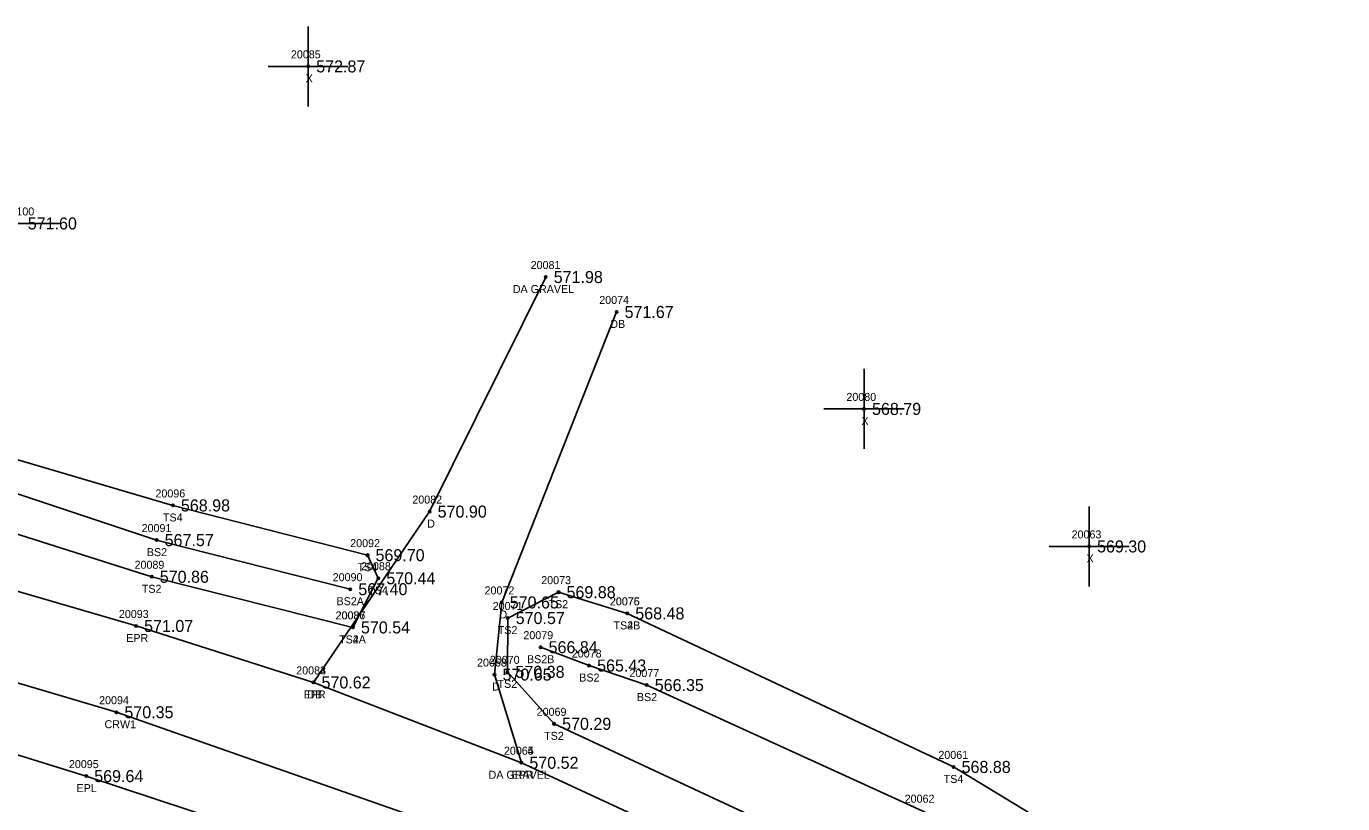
# Model space of a CAD drawing. Extents: x 1530159 to 1531652, y 877045 to 877724.
# Drawn here: x 1531368.6 to 1531533, y 877234.2 to 877331.3 of the extents above; entities that cross this region are included whole.
import ezdxf

# ---------------------------------------------------------------- set-up
doc = ezdxf.new("R2010")
doc.units = 0
for name, color, linetype in [('RD_DTM_BkLn1', 7, 'Continuous'), ('RD_DTM_BkLn2', 7, 'Continuous'), ('RD_DTM_BkLn_txCode', 7, 'Continuous'), ('RD_EX_Driveway', 7, 'Continuous'), ('RD_EX_Driveway_txCode', 7, 'Continuous'), ('RD_EX_Misc', 7, 'Continuous'), ('RD_EX_Misc_txCode', 7, 'Continuous'), ('RD_EX_Road', 7, 'Continuous'), ('RD_EX_Road_txCode', 7, 'Continuous'), ('RD_EX_TX_Driveway_ELEV', 7, 'Continuous'), ('RD_EX_TX_Misc_ELEV', 7, 'Continuous'), ('RD_EX_TX_Road_ELEV', 7, 'Continuous'), ('RD_HC_Survey_ELEV', 7, 'Continuous'), ('RD_HC_Survey_txCode', 7, 'Continuous'), ('RD_SMD_Locator', 7, 'Continuous')]:
    doc.layers.add(name, color=color, linetype=linetype)

msp = doc.modelspace()

# ---------------------------------------------------------------- linework, layer by layer
at = {"layer": 'RD_DTM_BkLn1'}
msp.add_lwpolyline([(1531601.44, 877127.51), (1531558.79, 877158.11), (1531516.37, 877185.16), (1531470.77, 877211.58), (1531426.8, 877229.22), (1531379.86, 877245.66), (1531330.99, 877260.09), (1531284.24, 877270.97), (1531236.44, 877276.73), (1531185.96, 877281.19), (1531132.29, 877281.48), (1531081.11, 877280.78), (1531028.25, 877278.4), (1530978.85, 877276.13), (1530941.18, 877274.78)], dxfattribs=at)
at = {"layer": 'RD_DTM_BkLn2'}
for points in [[(1531409.41, 877256.25), (1531384.28, 877262.57), (1531334.79, 877278.27), (1531300.27, 877288.3), (1531298.03, 877289.26), (1531298.58, 877295.92), (1531302.2, 877294.56)], [(1531409.41, 877256.25), (1531412.58, 877262.39), (1531411.23, 877265.27), (1531386.92, 877271.48), (1531336.7, 877286.23), (1531302.2, 877294.56)], [(1531409.08, 877261.02), (1531384.89, 877267.15), (1531335.68, 877283.49), (1531301.38, 877292.22)], [(1531525.39, 877208.9), (1531521.42, 877207.77), (1531476.95, 877224.45), (1531434.54, 877244.21), (1531428.71, 877250.7), (1531428.74, 877257.42), (1531435.09, 877260.65), (1531443.68, 877258)], [(1531525.39, 877208.9), (1531525.4, 877213.95), (1531484.44, 877238.83), (1531443.68, 877258)], [(1531522.55, 877211.98), (1531480.51, 877233.36), (1531446.11, 877249.05), (1531438.91, 877251.49), (1531432.85, 877253.78)]]:
    msp.add_lwpolyline(points, dxfattribs=at)
at = {"layer": 'RD_EX_Driveway'}
for points in [[(1531433.49, 877300), (1531418.99, 877270.71), (1531404.48, 877249.38)], [(1531430.45, 877239.35), (1531427.09, 877250.36), (1531428, 877259.37), (1531442.34, 877295.64)]]:
    msp.add_lwpolyline(points, dxfattribs=at)
at = {"layer": 'RD_EX_Misc'}
for p, q in [((1531403.82, 877321.3), (1531403.82, 877331.3)), ((1531398.82, 877326.3), (1531408.82, 877326.3)), ((1531362.79, 877306.69), (1531372.79, 877306.69)), ((1531473.25, 877278.53), (1531473.25, 877288.53)), ((1531468.25, 877283.53), (1531478.25, 877283.53)), ((1531501.36, 877261.36), (1531501.36, 877271.36)), ((1531496.36, 877266.36), (1531506.36, 877266.36))]:
    msp.add_line(p, q, dxfattribs=at)
at = {"layer": 'RD_EX_Road'}
for points in [[(1531606.64, 877133.84), (1531579.15, 877155.05), (1531564.87, 877165.27), (1531535.22, 877186.03), (1531511.53, 877200.27), (1531474.57, 877218.9), (1531430.45, 877239.35), (1531404.48, 877249.38), (1531382.32, 877256.43), (1531333.23, 877270.71), (1531303.67, 877277.44), (1531276.52, 877282.71), (1531237.32, 877287.2), (1531185.8, 877290.94), (1531132.61, 877292.77), (1531081.11, 877292.38), (1531038.69, 877288.67), (1530976.42, 877285.45), (1530941.06, 877284.26)], [(1531595.27, 877120.27), (1531553.56, 877149.9), (1531509.97, 877177.57), (1531465.94, 877201.73), (1531423.65, 877222), (1531376.09, 877237.68), (1531328.84, 877252.31), (1531282.81, 877261.85), (1531235.7, 877268.49), (1531185.47, 877272.84), (1531132.72, 877273.12), (1531080.2, 877271.87), (1531029.21, 877269.53), (1530978.47, 877268.32), (1530945.95, 877265.93), (1530941.45, 877262.44)]]:
    msp.add_lwpolyline(points, dxfattribs=at)
at = {"layer": 'RD_SMD_Locator'}
for centre in [(1531403.82, 877326.3), (1531433.49, 877300), (1531442.34, 877295.64), (1531473.25, 877283.53), (1531386.92, 877271.48), (1531418.99, 877270.71), (1531384.89, 877267.15), (1531501.36, 877266.36), (1531411.23, 877265.27), (1531384.28, 877262.57), (1531412.58, 877262.39), (1531409.08, 877261.02), (1531435.09, 877260.65), (1531428, 877259.37), (1531443.68, 877258), (1531443.68, 877258), (1531382.32, 877256.43), (1531409.41, 877256.25), (1531409.41, 877256.25), (1531428.74, 877257.42), (1531432.85, 877253.78), (1531438.91, 877251.49), (1531427.09, 877250.36), (1531428.71, 877250.7), (1531404.48, 877249.38), (1531404.48, 877249.38), (1531446.11, 877249.05), (1531379.86, 877245.66), (1531434.54, 877244.21), (1531430.45, 877239.35), (1531430.45, 877239.35), (1531484.44, 877238.83), (1531376.09, 877237.68)]:
    msp.add_circle(centre, 0.15, dxfattribs=at)

# ---------------------------------------------------------------- texts
at = {"layer": 'RD_DTM_BkLn_txCode'}
for s, p in [('20096', (1531384.74, 877272.48)), ('TS4', (1531385.68, 877269.48)), ('20091', (1531383.01, 877268.15)), ('20092', (1531409.07, 877266.27)), ('BS2', (1531383.66, 877265.15)), ('20089', (1531382.13, 877263.57)), ('20090', (1531406.88, 877262.02)), ('TS4', (1531409.99, 877263.27)), ('20088', (1531410.42, 877263.39)), ('TS2', (1531383.04, 877260.57)), ('TS4', (1531411.34, 877260.39)), ('20073', (1531432.93, 877261.65)), ('BS2A', (1531407.36, 877259.02)), ('TS2', (1531433.84, 877258.65)), ('20076', (1531441.5, 877259)), ('20075', (1531441.52, 877259)), ('20086', (1531407.23, 877257.25)), ('20087', (1531407.26, 877257.25)), ('20071', (1531426.87, 877258.42)), ('TS2', (1531427.5, 877255.42)), ('TS2B', (1531441.96, 877256)), ('TS4B', (1531441.96, 877256)), ('TS2A', (1531407.68, 877254.25)), ('TS4A', (1531407.68, 877254.25)), ('20079', (1531430.7, 877254.78)), ('20078', (1531436.75, 877252.49)), ('20070', (1531426.51, 877251.7)), ('BS2B', (1531431.15, 877251.78)), ('BS2', (1531437.68, 877249.49)), ('20077', (1531443.95, 877250.05)), ('TS2', (1531427.47, 877248.7)), ('BS2', (1531444.88, 877247.05)), ('20069', (1531432.36, 877245.21)), ('TS2', (1531433.29, 877242.21)), ('20061', (1531482.54, 877239.83)), ('TS4', (1531483.2, 877236.83)), ('20062', (1531478.33, 877234.36))]:
    msp.add_text(s, height=1, dxfattribs=at).set_placement(p)
at = {"layer": 'RD_EX_Driveway_txCode'}
for s, p in [('20081', (1531431.61, 877301)), ('DA GRAVEL', (1531429.38, 877298)), ('20074', (1531440.18, 877296.64)), ('DB', (1531441.56, 877293.64)), ('20082', (1531416.83, 877271.71)), ('D', (1531418.68, 877268.71)), ('20072', (1531425.85, 877260.37)), ('D', (1531427.7, 877257.37)), ('20068', (1531424.91, 877251.36)), ('20083', (1531402.32, 877250.38)), ('DB', (1531403.7, 877247.38)), ('D', (1531426.79, 877248.36)), ('20065', (1531428.27, 877240.35)), ('DA GRAVEL', (1531426.35, 877237.35))]:
    msp.add_text(s, height=1, dxfattribs=at).set_placement(p)
at = {"layer": 'RD_EX_Misc_txCode'}
for s, p in [('20085', (1531401.66, 877327.3)), ('X', (1531403.5, 877324.3)), ('20100', (1531365.88, 877307.69)), ('20080', (1531471.05, 877284.53)), ('X', (1531472.93, 877281.53)), ('20063', (1531499.18, 877267.36)), ('X', (1531501.05, 877264.36))]:
    msp.add_text(s, height=1, dxfattribs=at).set_placement(p)
at = {"layer": 'RD_EX_Road_txCode'}
for s, p in [('20093', (1531380.17, 877257.43)), ('EPR', (1531381.09, 877254.43)), ('20084', (1531402.32, 877250.38)), ('EPR', (1531403.25, 877247.38)), ('20064', (1531428.27, 877240.35)), ('20095', (1531373.93, 877238.68)), ('EPR', (1531429.22, 877237.35)), ('EPL', (1531374.88, 877235.68))]:
    msp.add_text(s, height=1, dxfattribs=at).set_placement(p)
at = {"layer": 'RD_EX_TX_Driveway_ELEV'}
for s, p in [('571.98', (1531434.49, 877299.25)), ('571.67', (1531443.34, 877294.89)), ('570.90', (1531419.99, 877269.96)), ('570.65', (1531429, 877258.62)), ('570.62', (1531405.48, 877248.63)), ('570.65', (1531428.09, 877249.61)), ('570.52', (1531431.45, 877238.6))]:
    msp.add_text(s, height=1.5, dxfattribs=at).set_placement(p)
at = {"layer": 'RD_EX_TX_Misc_ELEV'}
for s, p in [('572.87', (1531404.82, 877325.55)), ('571.60', (1531368.79, 877305.94)), ('568.79', (1531474.25, 877282.78)), ('568.98', (1531387.92, 877270.73)), ('567.57', (1531385.89, 877266.4)), ('569.30', (1531502.36, 877265.61)), ('569.70', (1531412.23, 877264.52)), ('570.86', (1531385.28, 877261.82)), ('570.44', (1531413.58, 877261.64)), ('567.40', (1531410.08, 877260.27)), ('569.88', (1531436.09, 877259.9)), ('570.57', (1531429.74, 877256.67)), ('568.48', (1531444.68, 877257.25)), ('568.48', (1531444.68, 877257.25)), ('570.54', (1531410.41, 877255.5)), ('570.54', (1531410.41, 877255.5)), ('566.84', (1531433.85, 877253.03)), ('570.38', (1531429.71, 877249.95)), ('565.43', (1531439.91, 877250.74)), ('566.35', (1531447.11, 877248.3)), ('570.29', (1531435.54, 877243.46)), ('568.88', (1531485.44, 877238.08))]:
    msp.add_text(s, height=1.5, dxfattribs=at).set_placement(p)
at = {"layer": 'RD_EX_TX_Road_ELEV'}
for s, p in [('571.07', (1531383.32, 877255.68)), ('570.62', (1531405.48, 877248.63)), ('570.52', (1531431.45, 877238.6)), ('569.64', (1531377.09, 877236.93))]:
    msp.add_text(s, height=1.5, dxfattribs=at).set_placement(p)
at = {"layer": 'RD_HC_Survey_ELEV'}
msp.add_text('570.35', height=1.5, dxfattribs=at).set_placement((1531380.86, 877244.91))
at = {"layer": 'RD_HC_Survey_txCode'}
for s, p in [('20094', (1531377.7, 877246.66)), ('CRW1', (1531378.38, 877243.66))]:
    msp.add_text(s, height=1, dxfattribs=at).set_placement(p)

doc.saveas('drawing.dxf')
